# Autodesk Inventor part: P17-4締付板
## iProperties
Created: 2008-07
Part Number: P17-4締付板
Document SubType Name: Modeling
Designer: y-shimohigashi
Density: 1 g/cm^3
Stock Number: P17-4締付板
Author: y-shimohigashi
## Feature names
1. 押し出し1 [Extrusion]
2. 穴1 [Hole]
